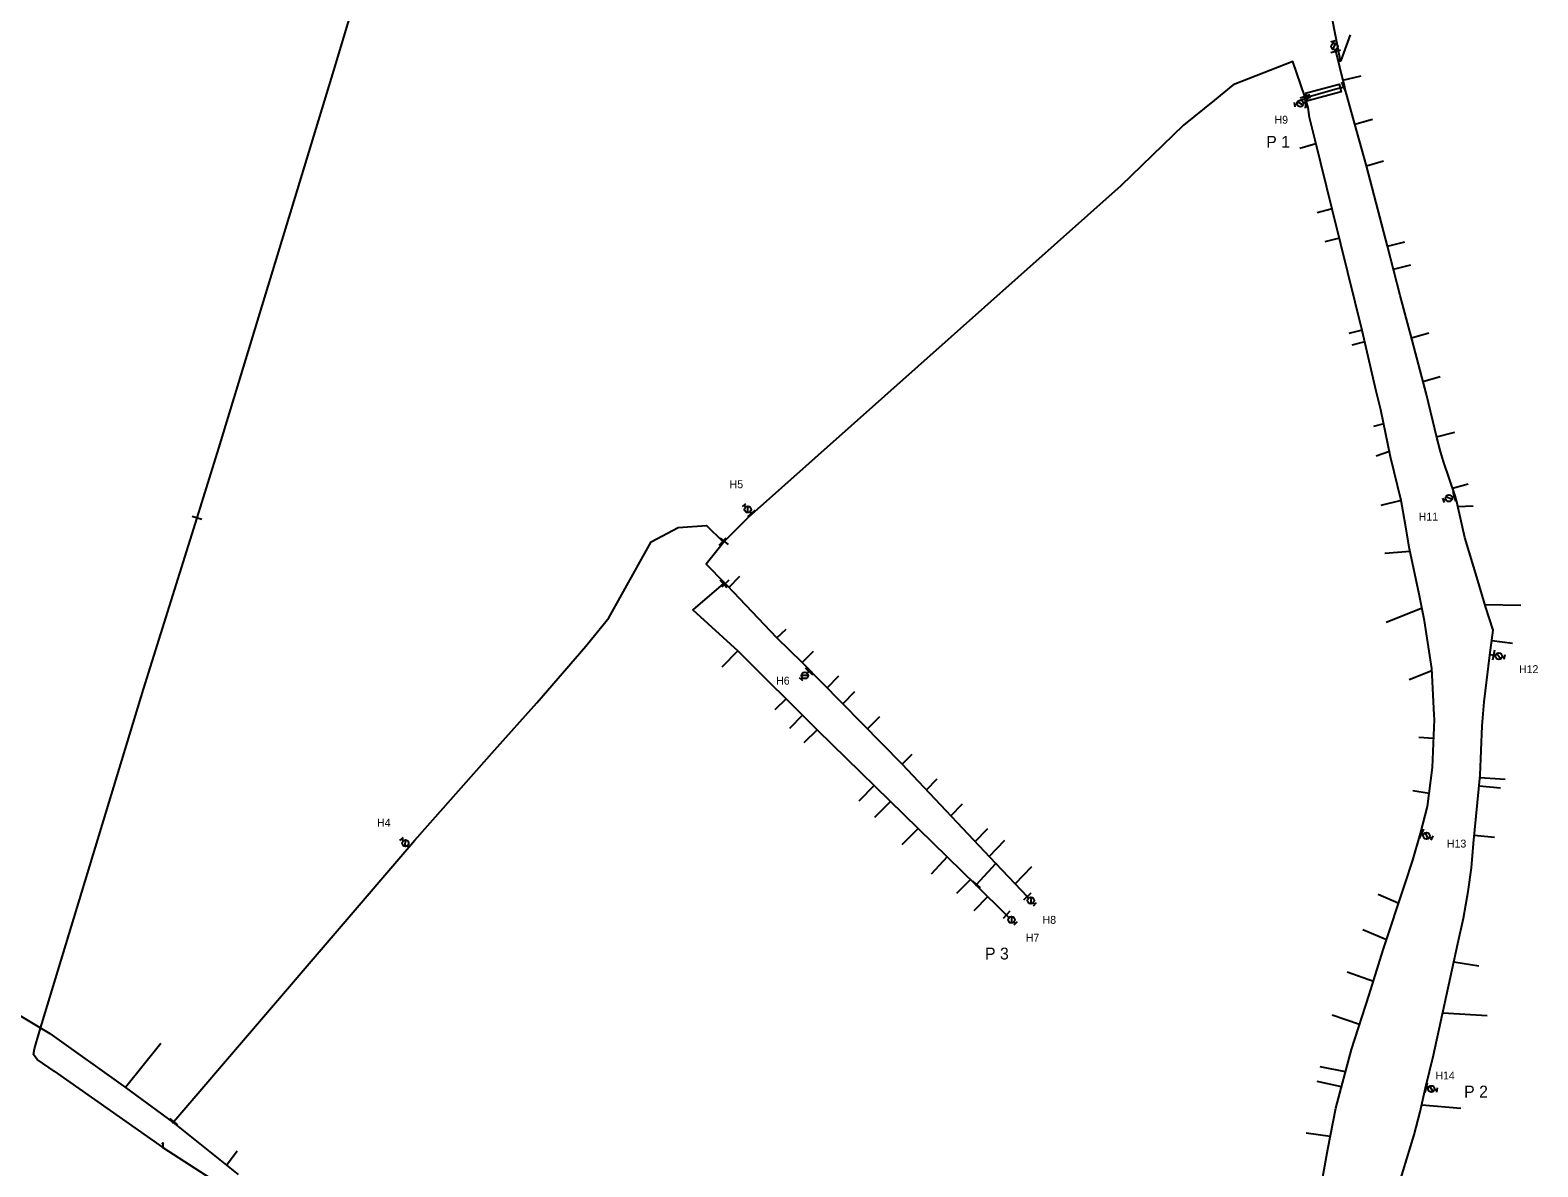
# Model space of a CAD drawing. Extents: x -548873 to -538270, y -1201997 to -1192514.
# Drawn here: x -547483.6 to -547101.8, y -1201240.2 to -1200952.2 of the extents above; entities that cross this region are included whole.
import ezdxf

# ---------------------------------------------------------------- set-up
doc = ezdxf.new("R2010")
doc.units = 0
for name, color, linetype in [('KN_HRAN_STÁTNÍ', 7, 'Continuous'), ('KN_PARC_Č', 7, 'Continuous'), ('KN_VKP_HRAN_SPORNÁ', 7, 'Continuous'), ('PK_PARC_Čv', 7, 'Continuous'), ('Vrstva 29', 7, 'Continuous'), ('Vrstva 37', 7, 'Continuous'), ('Vrstva 39', 7, 'Continuous')]:
    doc.layers.add(name, color=color, linetype=linetype)

# ---------------------------------------------------------------- blocks, each defined once
blk = doc.blocks.new('160')
at = {"layer": 'KN_HRAN_STÁTNÍ'}
blk.add_circle((0, 0), 0.0458, dxfattribs=at)
blk = doc.blocks.new('147')
at = {"layer": 'KN_HRAN_STÁTNÍ'}
blk.add_line((0, 1.27), (0, -1.27), dxfattribs=at)
blk = doc.blocks.new('133')
at = {"layer": 'KN_HRAN_STÁTNÍ'}
for p, q in [((0.28, 0), (0, 0)), ((0.54, 0.58), (1.7, -0.58)), ((1.94, 0), (2.52, 0)), ((2.52, 0.58), (2.52, -0.58))]:
    blk.add_line(p, q, dxfattribs=at)
blk.add_circle((1.11, 0), 0.825, dxfattribs=at)
blk = doc.blocks.new('150')
at = {"layer": 'KN_HRAN_STÁTNÍ'}
blk.add_line((0, 1.27), (0, -1.27), dxfattribs=at)
blk = doc.blocks.new('123')
at = {"layer": 'KN_HRAN_STÁTNÍ'}
for p, q in [((-0.26, 0.96), (0.26, 0.96)), ((-0.19, 1.13), (0.19, 0.79)), ((-0.19, 0.79), (0, 0.96)), ((0, 1.22), (0, 0.96)), ((0, 0.96), (0.19, 1.13)), ((0, 0.96), (0, 0))]:
    blk.add_line(p, q, dxfattribs=at)

msp = doc.modelspace()

# ---------------------------------------------------------------- linework, layer by layer
at = {"layer": 'KN_PARC_Č'}
for points in [[(-547152.374, -1200959.847), (-547151.804, -1200959.62), (-547171.999, -1200855.89), (-547165.66, -1200853.71)], [(-547152.284, -1200960.214), (-547151.556, -1200959.926), (-547149.228, -1200953.385)], [(-547151.14, -1200964.878), (-547146.522, -1200963.812)], [(-547160.153, -1200971.06), (-547160.592, -1200971.243), (-547160.647, -1200972.013)], [(-547148.145, -1200976.013), (-547143.639, -1200974.776)], [(-547157.958, -1200981.029), (-547162.023, -1200982.194)], [(-547145.16, -1200986.63), (-547140.879, -1200985.356)], [(-547153.885, -1200997.5), (-547157.646, -1200998.494)], [(-547152.004, -1201004.918), (-547155.716, -1201005.882)], [(-547139.837, -1201006.962), (-547135.457, -1201005.811)], [(-547138.336, -1201012.782), (-547133.921, -1201011.644)], [(-547146.288, -1201028.225), (-547149.589, -1201029.096)], [(-547145.613, -1201031.144), (-547148.826, -1201031.991)], [(-547133.737, -1201030.201), (-547129.388, -1201028.865)], [(-547130.845, -1201041.22), (-547126.516, -1201039.969)], [(-547140.759, -1201051.962), (-547143.388, -1201052.652)], [(-547127.405, -1201055.246), (-547122.813, -1201054.03)], [(-547139.32, -1201058.932), (-547142.674, -1201060.128)], [(-547123.375, -1201068.252), (-547119.372, -1201067.122)], [(-547136.346, -1201071.374), (-547141.505, -1201072.664)], [(-547122.013, -1201072.851), (-547118.128, -1201072.709)], [(-547134.071, -1201084.329), (-547140.517, -1201084.781)], [(-547306.613, -1201093.391), (-547303.806, -1201090.542)], [(-547131.072, -1201098.643), (-547140.18, -1201102.302)], [(-547115.13, -1201097.749), (-547106.073, -1201097.922)], [(-547294.48, -1201106.183), (-547292.153, -1201103.976)], [(-547113.419, -1201106.856), (-547108.168, -1201107.47)], [(-547304.333, -1201109.415), (-547308.375, -1201113.545)], [(-547288.098, -1201112.408), (-547285.211, -1201109.496)], [(-547281.77, -1201118.825), (-547278.799, -1201115.797)], [(-547128.611, -1201114.48), (-547134.359, -1201116.79)], [(-547277.797, -1201122.855), (-547274.738, -1201119.787)], [(-547292.084, -1201121.647), (-547294.951, -1201124.393)], [(-547288.007, -1201125.719), (-547291.26, -1201129.14)], [(-547271.533, -1201129.207), (-547268.36, -1201126.105)], [(-547284.286, -1201129.436), (-547287.622, -1201132.777)], [(-547128.142, -1201131.65), (-547131.864, -1201131.389)], [(-547262.701, -1201138.163), (-547260.192, -1201135.618)], [(-547256.6, -1201144.64), (-547253.861, -1201141.861)], [(-547116.419, -1201141.508), (-547109.992, -1201141.921)], [(-547269.852, -1201143.543), (-547273.693, -1201147.521)], [(-547129.275, -1201145.619), (-547133.414, -1201144.896)], [(-547116.579, -1201143.614), (-547111.247, -1201144.12)], [(-547265.67, -1201147.63), (-547269.733, -1201151.68)], [(-547250.417, -1201151.204), (-547247.444, -1201148.188)], [(-547258.727, -1201154.416), (-547262.856, -1201158.566)], [(-547244.275, -1201157.724), (-547241.071, -1201154.48)], [(-547240.701, -1201161.518), (-547236.708, -1201157.408)], [(-547117.85, -1201156.139), (-547112.706, -1201156.658)], [(-547251.369, -1201161.613), (-547255.361, -1201166.011)], [(-547234.161, -1201168.46), (-547229.865, -1201164.096)], [(-547245.442, -1201167.411), (-547248.947, -1201170.875)], [(-547241.047, -1201171.706), (-547244.57, -1201175.275)], [(-547136.981, -1201173.416), (-547142.214, -1201171.169)], [(-547140.048, -1201182.677), (-547146.049, -1201180.099)], [(-547123.04, -1201188.266), (-547116.74, -1201189.239)], [(-547143.406, -1201193.174), (-547150.083, -1201190.844)], [(-547146.942, -1201204.131), (-547153.857, -1201201.739)], [(-547125.861, -1201201.122), (-547114.601, -1201201.793)], [(-547459.442, -1201219.995), (-547450.465, -1201208.863)], [(-547150.492, -1201216.123), (-547156.875, -1201214.783)], [(-547151.486, -1201219.888), (-547157.678, -1201218.565)], [(-547131.169, -1201224.413), (-547121.236, -1201225.314)], [(-547154.321, -1201232.466), (-547160.465, -1201231.642)], [(-547433.814, -1201239.767), (-547431.105, -1201236.11)]]:
    msp.add_lwpolyline(points, dxfattribs=at)
at = {"layer": 'KN_VKP_HRAN_SPORNÁ'}
for points in [[(-547441.3, -1201075.798), (-547435.78, -1201058.15), (-547406.7, -1200962.45), (-547384.86, -1200889.95), (-547360.22, -1200808.53), (-547336.27, -1200731.53), (-547315.89, -1200665.18), (-547299.67, -1200611.78), (-547283.68, -1200552.68), (-547283.05, -1200548.6)], [(-547152.9, -1200957.7), (-547151.034, -1200965.313), (-547150.73, -1200966.55)], [(-547160.735, -1200969.065), (-547163.81, -1200960.14), (-547178.88, -1200966.05), (-547183.61, -1200969.99), (-547191.532, -1200976.312), (-547207.367, -1200991.705), (-547301.696, -1201075.654), (-547307.82, -1201081.73)], [(-547160.653, -1200969.329), (-547160.3, -1200969.18), (-547152.79, -1200967.11), (-547151.81, -1200966.87), (-547150.914, -1200966.601)], [(-547150.914, -1200966.601), (-547150.73, -1200966.55)], [(-547136.81, -1201244.2), (-547133.05, -1201232.01), (-547131.56, -1201226.18), (-547130.22, -1201220.13), (-547128.22, -1201211.87), (-547122.01, -1201183.57), (-547120.58, -1201177.13), (-547119.4, -1201170.41), (-547118.599, -1201164.412), (-547118.06, -1201158.28), (-547116.36, -1201140.91), (-547115.83, -1201128.42), (-547115.36, -1201122.35), (-547113.94, -1201110.53), (-547113.04, -1201104.19), (-547115, -1201098.18), (-547116.98, -1201091.64), (-547120.28, -1201080.71), (-547120.8, -1201078.09), (-547122.27, -1201071.74), (-547122.69, -1201070.23), (-547125.66, -1201061.52), (-547126.43, -1201059), (-547127.37, -1201055.39), (-547129.98, -1201044.52), (-547133.59, -1201030.75), (-547136.61, -1201019.48), (-547139.85, -1201006.91), (-547145.16, -1200986.63), (-547148.13, -1200976.07), (-547150.44, -1200967.48), (-547150.73, -1200966.55)], [(-547160.653, -1200969.329), (-547160.735, -1200969.065)], [(-547160.579, -1200969.574), (-547160.611, -1200969.462), (-547160.653, -1200969.329)], [(-547157.63, -1201250.65), (-547154.96, -1201235.71), (-547152.9, -1201225.25), (-547148.98, -1201210.39), (-547144.48, -1201196.57), (-547140.89, -1201185.22), (-547135.32, -1201168.4), (-547133.43, -1201162.46), (-547131.45, -1201155.69), (-547129.69, -1201148.85), (-547128.42, -1201138.97), (-547127.96, -1201126.87), (-547127.99, -1201125.65), (-547128.64, -1201113.96), (-547130.43, -1201101.85), (-547131.78, -1201095.11), (-547134.23, -1201083.58), (-547135.26, -1201077.61), (-547136.348, -1201071.361), (-547139.04, -1201060.29), (-547141.49, -1201048.42), (-547142.71, -1201043.7), (-547146.27, -1201028.3), (-547151.61, -1201006.47), (-547153.87, -1200997.56), (-547158.19, -1200980.09), (-547159.55, -1200974.39), (-547159.94, -1200971.83), (-547160.01, -1200971.56), (-547160.579, -1200969.574)], [(-547477.46, -1201215.95), (-547481.82, -1201212.98), (-547482.74, -1201211.69), (-547482.5, -1201210.24), (-547481.18, -1201205.85), (-547454.86, -1201119.15), (-547441.3, -1201075.798)], [(-547447.19, -1201228.69), (-547386.13, -1201157.44), (-547366.01, -1201134.62), (-547355.22, -1201122.64), (-547342.81, -1201108.27), (-547337.03, -1201101.12), (-547326.29, -1201081.83), (-547319.46, -1201078.18), (-547312.28, -1201077.73), (-547308.192, -1201081.778)], [(-547307.977, -1201081.991), (-547312.41, -1201087.53), (-547307.727, -1201092.222)], [(-547308.192, -1201081.778), (-547308.085, -1201081.884), (-547307.977, -1201081.991)], [(-547307.82, -1201081.73), (-547307.977, -1201081.991)], [(-547307.958, -1201092.418), (-547315.753, -1201099.036), (-547304.321, -1201109.425), (-547284.294, -1201129.428), (-547258.726, -1201154.417), (-547244.012, -1201168.81)], [(-547307.727, -1201092.222), (-547307.958, -1201092.418)], [(-547307.517, -1201092.438), (-547307.727, -1201092.222)], [(-547238.978, -1201163.347), (-547262.713, -1201138.151), (-547288.101, -1201112.405), (-547294.477, -1201106.186), (-547306.965, -1201093.02), (-547307.517, -1201092.438)], [(-547611.91, -1201128.89), (-547610.7, -1201127.36), (-547609.26, -1201126.57), (-547607.51, -1201127.05), (-547597.84, -1201133.1), (-547584.99, -1201141.19), (-547566.47, -1201153.69), (-547539.9, -1201169.62), (-547478.55, -1201206.38), (-547459.404, -1201220.022), (-547447.389, -1201228.957)], [(-547243.881, -1201168.668), (-547238.978, -1201163.347)], [(-547238.978, -1201163.347), (-547231.109, -1201171.7)], [(-547244.012, -1201168.81), (-547243.881, -1201168.668)], [(-547244.012, -1201168.81), (-547236.366, -1201176.279)], [(-547477.46, -1201215.95), (-547449.986, -1201235.215)], [(-547447.389, -1201228.957), (-547447.19, -1201228.69)], [(-547447.389, -1201228.957), (-547430.869, -1201242.112)], [(-547449.986, -1201235.215), (-547435.21, -1201244.81), (-547406.63, -1201264.03), (-547392.99, -1201273.3), (-547381.08, -1201281.63), (-547367.01, -1201291.14), (-547360.83, -1201298.7), (-547353.81, -1201306.95), (-547341.67, -1201324.18), (-547336.99, -1201335.91), (-547329.24, -1201351.9), (-547327.295, -1201361.339), (-547323.293, -1201386.882), (-547316.891, -1201432.394), (-547314.523, -1201453.79), (-547312.399, -1201469.169), (-547309.22, -1201492.68), (-547308.13, -1201498.74), (-547302.55, -1201512.53), (-547298.32, -1201526.93), (-547292.491, -1201562.123)]]:
    msp.add_lwpolyline(points, dxfattribs=at)
at = {"layer": 'PK_PARC_Čv'}
for points in [[(-547152.9, -1200957.7), (-547152.97, -1200957.45)], [(-547160.313, -1200970.501), (-547160.615, -1200970.554), (-547160.82, -1200970.59)], [(-547122.69, -1201070.229), (-547122.94, -1201070.28), (-547123.21, -1201070.36)], [(-547300.771, -1201074.831), (-547301.1, -1201074.45)], [(-547113.923, -1201110.409), (-547112.75, -1201110.57)], [(-547286.135, -1201114.399), (-547286.6, -1201114.864)], [(-547131.45, -1201155.69), (-547131.26, -1201155.79), (-547131.01, -1201155.87)], [(-547387.622, -1201159.181), (-547387.8, -1201158.98)], [(-547231.109, -1201171.7), (-547230.93, -1201171.89)], [(-547236.366, -1201176.279), (-547235.855, -1201176.789)], [(-547130.22, -1201220.13), (-547130.1, -1201220.17), (-547129.84, -1201220.21)]]:
    msp.add_lwpolyline(points, dxfattribs=at)
at = {"layer": 'Vrstva 37'}
msp.add_lwpolyline([(-547160.563, -1200968.215), (-547152.073, -1200965.905), (-547151.547, -1200967.835), (-547160.037, -1200970.145), (-547160.563, -1200968.215)], dxfattribs=at)

# ---------------------------------------------------------------- block references
at = {"layer": 'PK_PARC_Čv'}
for name, p, xscale, yscale, rotation in [('133', (-547152.97, -1200957.45), 0.9999999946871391, 0.9999999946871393, 106.00000024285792), ('150', (-547152.923, -1200957.618), 0.9999999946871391, 0.9999999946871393, -73.99999975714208), ('133', (-547160.82, -1200970.59), 1.0073309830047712, 1.0073309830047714, -167.86109133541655), ('150', (-547160.615, -1200970.554), 1.0073309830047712, 1.0073309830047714, 12.13890866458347), ('133', (-547123.21, -1201070.36), 1.035124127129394, 1.0351241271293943, -157.49634583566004), ('150', (-547122.94, -1201070.28), 0.999999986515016, 0.9999999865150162, 15.000000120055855), ('133', (-547301.1, -1201074.45), 1.0000000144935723, 1.0000000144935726, 130.99999910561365), ('150', (-547300.936, -1201074.641), 1.0000000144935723, 1.0000000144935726, -49.00000089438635), ('150', (-547112.999, -1201110.536), 1.0098116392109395, 1.0098116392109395, -10.610301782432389), ('133', (-547112.75, -1201110.57), 1.0098116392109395, 1.0098116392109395, -10.610301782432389), ('133', (-547286.6, -1201114.864), 1.0000000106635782, 1.0000000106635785, -134.00000165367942), ('150', (-547286.361, -1201114.625), 1.0000000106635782, 1.0000000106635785, 45.99999834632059), ('133', (-547387.8, -1201158.98), 1.0000000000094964, 1.0000000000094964, 132.0000013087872), ('150', (-547131.26, -1201155.79), 1.025136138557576, 1.025136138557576, -25.2507584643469), ('133', (-547131.01, -1201155.87), 1.035124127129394, 1.0351241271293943, -22.503654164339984), ('150', (-547231.076, -1201171.735), 1.0000000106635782, 1.0000000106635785, -45.99999834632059), ('133', (-547230.93, -1201171.89), 1.0000000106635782, 1.0000000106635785, -45.99999834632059), ('150', (-547236.313, -1201176.332), 1.0000000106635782, 1.0000000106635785, -44.00000165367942), ('133', (-547235.855, -1201176.789), 1.0000000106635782, 1.0000000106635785, -44.00000165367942), ('150', (-547130.1, -1201220.17), 1.0028916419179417, 1.0028916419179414, -13.69720873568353), ('133', (-547129.84, -1201220.21), 1.0092050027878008, 1.0092050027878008, -11.116918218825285)]:
    msp.add_blockref(name, p, dxfattribs=dict(at, xscale=xscale, yscale=yscale, rotation=rotation))
at = {"layer": 'Vrstva 29'}
for name, p, xscale, yscale, rotation in [('160', (-547152.9, -1200957.7), 1.0000000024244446, 1.0000000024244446, -75.99999967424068), ('147', (-547150.914, -1200966.601), 1.0365458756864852, 1.0365458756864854, -158.02850914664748), ('160', (-547150.73, -1200966.55), 0.9999999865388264, 0.9999999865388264, -120.00000044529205), ('147', (-547160.735, -1200969.065), 0.999999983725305, 0.999999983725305, -70.99999877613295), ('147', (-547160.579, -1200969.574), 0.9999999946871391, 0.9999999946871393, 106.00000024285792), ('160', (-547160.653, -1200969.329), 1.000000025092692, 1.0000000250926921, 108.00000002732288), ('147', (-547441.3, -1201075.798), 0.9999999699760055, 0.9999999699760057, -106.99999966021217), ('147', (-547308.192, -1201081.778), 1.0000000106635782, 1.0000000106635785, 135.99999834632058), ('147', (-547307.82, -1201081.73), 1.000000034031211, 1.0000000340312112, 51.999999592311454), ('160', (-547307.977, -1201081.991), 1.0000000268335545, 1.0000000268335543, -86.00000028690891), ('147', (-547307.958, -1201092.418), 1.0000000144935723, 1.0000000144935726, 40.99999910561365), ('147', (-547307.517, -1201092.438), 1.0000000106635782, 1.0000000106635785, -45.99999834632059), ('160', (-547307.727, -1201092.222), 1.00000001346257, 1.0000000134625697, -91.99999990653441), ('160', (-547238.978, -1201163.347), 1.0000000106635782, 1.0000000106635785, -45.99999834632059), ('147', (-547243.881, -1201168.668), 1.0000000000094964, 1.0000000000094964, -132.0000013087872), ('160', (-547244.012, -1201168.81), 1.00000001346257, 1.0000000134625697, -88.00000009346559), ('160', (-547231.109, -1201171.7), 1.0000000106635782, 1.0000000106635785, 134.00000165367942), ('160', (-547236.366, -1201176.279), 1.0000000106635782, 1.0000000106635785, 135.99999834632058), ('160', (-547477.46, -1201215.95), 0.9999999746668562, 0.999999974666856, 145.99999954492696), ('147', (-547447.19, -1201228.69), 1.000000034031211, 1.0000000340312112, -128.00000040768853), ('160', (-547447.389, -1201228.957), 1.008377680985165, 1.0083776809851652, -168.37362119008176), ('160', (-547449.986, -1201235.215), 0.9999999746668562, 0.999999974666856, 145.99999954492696)]:
    msp.add_blockref(name, p, dxfattribs=dict(at, xscale=xscale, yscale=yscale, rotation=rotation))
at = {"layer": 'Vrstva 39'}
msp.add_blockref('123', (-547449.986, -1201235.215), dxfattribs=at)

# ---------------------------------------------------------------- texts
at = {"layer": 'PK_PARC_Čv'}
for s, height, p in [('H9', 2, (-547168.44, -1200975.92)), ('P 1', 3, (-547170.54, -1200982.02)), ('H5', 2, (-547306.43, -1201068.25)), ('H11', 2, (-547131.93, -1201076.46)), ('H6', 2, (-547294.65, -1201118.004)), ('H12', 2, (-547106.53, -1201115.09)), ('H4', 2, (-547395.72, -1201153.98)), ('H13', 2, (-547124.79, -1201159.28)), ('H8', 2, (-547227.18, -1201178.59)), ('H7', 2, (-547231.415, -1201183.089)), ('P 3', 3, (-547241.755, -1201187.639)), ('H14', 2, (-547127.7, -1201218.01)), ('P 2', 3, (-547120.42, -1201222.59))]:
    msp.add_text(s, height=height, dxfattribs=at).set_placement(p)

doc.saveas('drawing.dxf')
